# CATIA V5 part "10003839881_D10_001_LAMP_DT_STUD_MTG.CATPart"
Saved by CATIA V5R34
Part number: 10003839881_D10_001
Revision: V01
Definition: LAMP_DT_STUD_MTG
Material "PC+ABS - Bayblend TX85F": density 1170 kg/m3, Young's modulus 2.2e+09 Pa, Poisson ratio 0.35
Bounding box of the stored display mesh (mm): x -104.789 to 104.787, y -32.295 to 32.295, z -57.2 to 0.338
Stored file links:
  C:\Users\kumaan57\sc5\win\10003839881_D10_001_LAMP_DT_STUD_MTG.CATPart
  C:\Users\kumaan57\sc5\win\10003666979_D10_001_HOUSING_WITH_STUD_6_PIN_DT_CONNECTOR_.CATPart
  C:\Users\kumaan57\sc5\win\10003666974_D10_001_OUTER_LENS_WITH_STUD.CATPart
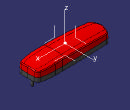
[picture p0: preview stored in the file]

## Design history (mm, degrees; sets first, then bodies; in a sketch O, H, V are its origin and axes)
AxisSystem1: origin (0, 0, 0), X (1, 0, 0), Y (0, 1, 0), Z (0, 0, 1)
Body1 (main body)
Body2 "LAMP"
  Solid1: solid without history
